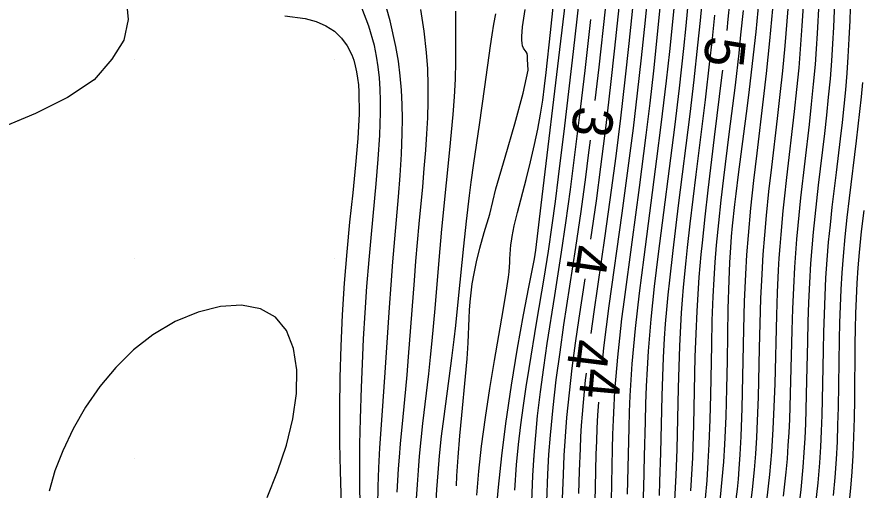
# Model space of a CAD drawing. Extents: x 2602990 to 2605851, y 618069 to 619180.
# Drawn here: x 2603504.11 to 2603546.38, y 618728.43 to 618752.12 of the extents above; entities that cross this region are included whole.
import ezdxf

# ---------------------------------------------------------------- set-up
doc = ezdxf.new("R2010")
doc.units = 0
for name, color, linetype in [('DTM Contours Major', 7, 'Continuous'), ('DTM Contours Major Text', 7, 'Continuous'), ('DTM Contours Minor', 7, 'Continuous'), ('DTM Contours Minor Text', 7, 'Continuous'), ('Exist DTM QL2 LIDAR Elevation Point', 7, 'Continuous')]:
    doc.layers.add(name, color=color, linetype=linetype)

msp = doc.modelspace()

# ---------------------------------------------------------------- linework, layer by layer
at = {"layer": 'DTM Contours Major'}
for points in [[(2603533.394, 618734.823), (2603533.474, 618735.547), (2603533.603, 618736.597), (2603533.742, 618737.653), (2603534.389, 618742.291), (2603534.722, 618744.789), (2603534.943, 618746.545), (2603535.151, 618748.306), (2603535.348, 618750.073), (2603535.543, 618751.946), (2603536.287, 618759.536)], [(2603524.101, 618727.991), (2603524.144, 618728.7), (2603524.194, 618729.409), (2603524.253, 618730.119), (2603524.333, 618730.94), (2603524.423, 618731.764), (2603524.714, 618734.251), (2603524.805, 618735.084), (2603524.886, 618735.893), (2603525.029, 618737.512), (2603525.23, 618739.939), (2603525.371, 618741.483), (2603525.6, 618743.805), (2603525.769, 618745.464), (2603525.855, 618746.346), (2603525.932, 618747.23), (2603525.997, 618748.114), (2603526.044, 618748.995), (2603526.069, 618749.872), (2603526.072, 618750.719), (2603526.06, 618752.402)], [(2603540.778, 618727.497), (2603540.897, 618728.462), (2603540.998, 618729.433), (2603541.065, 618730.242), (2603541.118, 618731.061), (2603541.159, 618731.898), (2603541.201, 618733.078), (2603541.259, 618735.529), (2603541.288, 618736.774), (2603541.326, 618738.014), (2603541.379, 618739.236), (2603541.438, 618740.22), (2603541.512, 618741.197), (2603541.6, 618742.178), (2603541.724, 618743.378), (2603541.861, 618744.593), (2603542.15, 618747.031), (2603542.288, 618748.233), (2603542.414, 618749.409), (2603542.533, 618750.669), (2603542.684, 618752.528)], [(2603533.008, 618726.521), (2603533.051, 618728.569), (2603533.089, 618730.23), (2603533.111, 618730.878), (2603533.138, 618731.525), (2603533.172, 618732.173), (2603533.213, 618732.825), (2603533.214, 618732.831)]]:
    msp.add_lwpolyline(points, dxfattribs=at)
at = {"layer": 'DTM Contours Minor'}
for points in [[(2603529.008, 618728.417), (2603529.101, 618729.684), (2603529.199, 618730.701), (2603529.315, 618731.693), (2603529.444, 618732.661), (2603529.582, 618733.604), (2603529.727, 618734.522), (2603530.123, 618736.887), (2603530.483, 618739.039), (2603530.694, 618740.389), (2603530.883, 618741.69), (2603531.044, 618742.873), (2603531.205, 618744.11), (2603531.52, 618746.67), (2603531.952, 618750.39), (2603532.604, 618756.134), (2603532.728, 618757.281), (2603532.846, 618758.417), (2603532.904, 618759.008)], [(2603503.501, 618758.444), (2603504.672, 618758.064), (2603505.794, 618757.541), (2603506.84, 618756.878), (2603507.779, 618756.075), (2603508.575, 618755.146), (2603509.19, 618754.123), (2603509.574, 618753.053), (2603509.68, 618751.979), (2603509.459, 618750.947), (2603508.863, 618750), (2603507.971, 618748.973), (2603506.648, 618748.083), (2603505.042, 618747.288), (2603503.3, 618746.547)], [(2603541.613, 618727.892), (2603541.764, 618729.206), (2603541.818, 618729.782), (2603541.865, 618730.35), (2603541.905, 618730.913), (2603541.939, 618731.474), (2603541.993, 618732.596), (2603542.032, 618733.738), (2603542.117, 618737.186), (2603542.154, 618738.318), (2603542.206, 618739.429), (2603542.242, 618740.031), (2603542.284, 618740.627), (2603542.331, 618741.219), (2603542.441, 618742.405), (2603542.503, 618743.005), (2603542.621, 618744.082), (2603543.003, 618747.382), (2603543.122, 618748.478), (2603543.228, 618749.56), (2603543.289, 618750.269), (2603543.393, 618751.667), (2603543.658, 618755.744)], [(2603528.879, 618741.121), (2603528.987, 618741.651), (2603529.151, 618742.331), (2603529.575, 618743.974), (2603529.796, 618744.855), (2603530, 618745.72), (2603530.164, 618746.501), (2603530.299, 618747.242), (2603530.412, 618747.954), (2603530.507, 618748.647), (2603530.59, 618749.335), (2603530.805, 618751.336), (2603531.221, 618755.282)], [(2603532.822, 618740.986), (2603533.095, 618742.911), (2603533.323, 618744.616), (2603533.581, 618746.676), (2603533.822, 618748.735), (2603534.024, 618750.556), (2603534.53, 618755.417)], [(2603529.996, 618740.004), (2603530.06, 618740.442), (2603530.341, 618742.696), (2603531.323, 618750.907), (2603531.734, 618754.38)], [(2603536.245, 618728.149), (2603536.275, 618728.863), (2603536.318, 618730.296), (2603536.385, 618733.149), (2603536.415, 618734.107), (2603536.455, 618735.064), (2603536.507, 618736.017), (2603536.558, 618736.744), (2603536.618, 618737.469), (2603536.686, 618738.197), (2603536.761, 618738.928), (2603536.928, 618740.417), (2603537.203, 618742.669), (2603537.779, 618747.24), (2603537.983, 618748.967), (2603538.175, 618750.709), (2603538.3, 618751.938), (2603538.542, 618754.46)], [(2603533.844, 618727.893), (2603533.9, 618730.493), (2603533.921, 618731.218), (2603533.948, 618731.941), (2603533.982, 618732.666), (2603534.024, 618733.394), (2603534.077, 618734.129), (2603534.161, 618735.075), (2603534.261, 618736.033), (2603534.374, 618736.999), (2603534.496, 618737.971), (2603534.882, 618740.841), (2603535.251, 618743.579), (2603535.587, 618746.191), (2603535.782, 618747.801), (2603535.966, 618749.417), (2603536.159, 618751.235), (2603536.459, 618754.271)], [(2603535.437, 618727.752), (2603535.465, 618728.541), (2603535.506, 618730.12), (2603535.546, 618731.867), (2603535.571, 618732.745), (2603535.603, 618733.624), (2603535.644, 618734.504), (2603535.698, 618735.385), (2603535.76, 618736.187), (2603535.832, 618736.991), (2603535.914, 618737.798), (2603536.005, 618738.611), (2603536.203, 618740.258), (2603537.013, 618746.592), (2603537.248, 618748.556), (2603537.466, 618750.536), (2603537.583, 618751.675), (2603537.809, 618754.013)], [(2603539.634, 618751.443), (2603539.693, 618752.01), (2603539.85, 618753.629)], [(2603544.078, 618727.771), (2603544.185, 618728.787), (2603544.271, 618729.793), (2603544.322, 618730.591), (2603544.359, 618731.384), (2603544.387, 618732.172), (2603544.421, 618733.745), (2603544.45, 618735.431), (2603544.47, 618736.334), (2603544.496, 618737.239), (2603544.531, 618738.145), (2603544.577, 618739.051), (2603544.637, 618739.957), (2603544.711, 618740.835), (2603544.797, 618741.711), (2603544.892, 618742.585), (2603545.099, 618744.325), (2603545.303, 618746.012), (2603545.397, 618746.831), (2603545.485, 618747.65), (2603545.565, 618748.47), (2603545.635, 618749.291), (2603545.694, 618750.116), (2603545.745, 618751.022), (2603545.784, 618751.932), (2603545.84, 618753.753)], [(2603522.159, 618727.631), (2603522.184, 618728.6), (2603522.219, 618729.538), (2603522.272, 618730.536), (2603522.383, 618732.167), (2603522.532, 618734.319), (2603522.744, 618737.572), (2603522.825, 618738.705), (2603522.914, 618739.847), (2603523.199, 618743.109), (2603523.281, 618744.181), (2603523.346, 618745.238), (2603523.385, 618746.28), (2603523.393, 618747.007), (2603523.382, 618747.728), (2603523.348, 618748.447), (2603523.288, 618749.167), (2603523.197, 618749.892), (2603523.072, 618750.626), (2603522.777, 618751.921), (2603522.413, 618753.235)], [(2603532.84, 618736.268), (2603532.989, 618737.343), (2603533.539, 618741.153), (2603533.856, 618743.436), (2603534.08, 618745.144), (2603534.315, 618747.051), (2603534.537, 618748.961), (2603534.735, 618750.783), (2603534.999, 618753.374)], [(2603543.197, 618727.341), (2603543.328, 618728.462), (2603543.433, 618729.568), (2603543.488, 618730.303), (2603543.531, 618731.029), (2603543.564, 618731.75), (2603543.59, 618732.468), (2603543.627, 618733.907), (2603543.668, 618735.86), (2603543.693, 618736.842), (2603543.726, 618737.824), (2603543.769, 618738.801), (2603543.827, 618739.771), (2603543.887, 618740.562), (2603543.957, 618741.347), (2603544.036, 618742.129), (2603544.21, 618743.689), (2603544.515, 618746.281), (2603544.617, 618747.191), (2603544.711, 618748.102), (2603544.797, 618749.013), (2603544.869, 618749.922), (2603544.924, 618750.765), (2603544.969, 618751.606), (2603545.041, 618753.285)], [(2603539.254, 618727.542), (2603539.392, 618728.953), (2603539.461, 618729.834), (2603539.516, 618730.713), (2603539.579, 618732.117), (2603539.62, 618733.515), (2603539.646, 618734.891), (2603539.688, 618737.507), (2603539.728, 618738.94), (2603539.769, 618739.817), (2603539.817, 618740.578), (2603539.859, 618741.116), (2603539.907, 618741.65), (2603540.018, 618742.72), (2603540.081, 618743.265), (2603540.201, 618744.23), (2603540.602, 618747.284), (2603540.737, 618748.335), (2603540.91, 618749.782), (2603541.079, 618751.365), (2603541.236, 618752.989)], [(2603542.46, 618728.115), (2603542.589, 618729.329), (2603542.646, 618729.996), (2603542.693, 618730.654), (2603542.732, 618731.305), (2603542.764, 618731.954), (2603542.811, 618733.252), (2603542.89, 618736.441), (2603542.921, 618737.503), (2603542.962, 618738.555), (2603543.017, 618739.592), (2603543.064, 618740.292), (2603543.12, 618740.986), (2603543.182, 618741.675), (2603543.324, 618743.054), (2603543.747, 618746.735), (2603543.858, 618747.739), (2603543.959, 618748.741), (2603544.047, 618749.735), (2603544.106, 618750.513), (2603544.156, 618751.286), (2603544.241, 618752.822)], [(2603521.309, 618726.64), (2603521.268, 618728.494), (2603521.256, 618729.566), (2603521.263, 618730.732), (2603521.291, 618731.99), (2603521.343, 618733.555), (2603521.392, 618734.75), (2603521.453, 618736), (2603521.528, 618737.293), (2603521.618, 618738.615), (2603521.725, 618739.952), (2603521.842, 618741.234), (2603522.084, 618743.765), (2603522.186, 618744.994), (2603522.26, 618746.187), (2603522.295, 618747.333), (2603522.294, 618747.923), (2603522.277, 618748.499), (2603522.24, 618749.061), (2603522.183, 618749.613), (2603522.101, 618750.154), (2603521.993, 618750.687), (2603521.72, 618751.652), (2603521.361, 618752.577)], [(2603523.138, 618728.331), (2603523.204, 618729.494), (2603523.245, 618730.073), (2603523.3, 618730.74), (2603523.427, 618732.09), (2603523.562, 618733.476), (2603523.628, 618734.189), (2603523.705, 618735.1), (2603523.991, 618738.913), (2603524.07, 618739.888), (2603524.237, 618741.751), (2603524.408, 618743.604), (2603524.488, 618744.525), (2603524.561, 618745.44), (2603524.617, 618746.257), (2603524.66, 618747.071), (2603524.685, 618747.884), (2603524.687, 618748.696), (2603524.662, 618749.511), (2603524.605, 618750.33), (2603524.48, 618751.407), (2603524.316, 618752.485)], [(2603525.06, 618727.614), (2603525.113, 618728.453), (2603525.176, 618729.299), (2603525.251, 618730.15), (2603525.356, 618731.134), (2603525.475, 618732.119), (2603525.862, 618735.033), (2603525.981, 618735.972), (2603526.061, 618736.666), (2603526.204, 618738.021), (2603526.462, 618740.633), (2603526.597, 618741.897), (2603526.75, 618743.183), (2603526.834, 618743.839), (2603526.963, 618744.791), (2603527.242, 618746.72), (2603527.52, 618748.615), (2603527.803, 618750.667), (2603527.883, 618751.216), (2603527.972, 618751.752), (2603528.074, 618752.277)], [(2603529.654, 618750), (2603529.652, 618750.168), (2603529.627, 618750.287), (2603529.588, 618750.372), (2603529.54, 618750.437), (2603529.489, 618750.493), (2603529.444, 618750.556), (2603529.401, 618750.66), (2603529.376, 618750.795), (2603529.365, 618750.959), (2603529.368, 618751.15), (2603529.383, 618751.369), (2603529.407, 618751.613), (2603529.53, 618752.49)], [(2603533.039, 618747.931), (2603533.233, 618749.606), (2603533.548, 618752.499)], [(2603534.654, 618728.215), (2603534.731, 618731.537), (2603534.757, 618732.338), (2603534.791, 618733.14), (2603534.833, 618733.945), (2603534.888, 618734.754), (2603534.96, 618735.629), (2603535.046, 618736.51), (2603535.144, 618737.397), (2603535.25, 618738.289), (2603535.479, 618740.09), (2603536.126, 618745.014), (2603536.34, 618746.718), (2603536.599, 618748.91), (2603536.761, 618750.39), (2603536.98, 618752.542)], [(2603538.555, 618728), (2603538.63, 618728.913), (2603538.69, 618729.819), (2603538.736, 618730.729), (2603538.78, 618731.957), (2603538.811, 618733.2), (2603538.861, 618735.689), (2603538.893, 618736.914), (2603538.938, 618738.112), (2603538.983, 618738.978), (2603539.039, 618739.833), (2603539.107, 618740.686), (2603539.212, 618741.808), (2603539.331, 618742.934), (2603539.461, 618744.055), (2603539.733, 618746.24), (2603540.044, 618748.7), (2603540.229, 618750.295), (2603540.327, 618751.215), (2603540.449, 618752.442)], [(2603540.088, 618727.976), (2603540.145, 618728.479), (2603540.195, 618728.98), (2603540.24, 618729.486), (2603540.293, 618730.215), (2603540.341, 618731.104), (2603540.388, 618732.531), (2603540.465, 618736.482), (2603540.504, 618737.86), (2603540.564, 618739.237), (2603540.622, 618740.202), (2603540.695, 618741.168), (2603540.821, 618742.543), (2603540.968, 618743.924), (2603541.129, 618745.3), (2603541.455, 618747.991), (2603541.605, 618749.285), (2603541.775, 618750.916), (2603541.925, 618752.524)], [(2603517.513, 618752.166), (2603518.532, 618752.039), (2603519.086, 618751.886), (2603519.571, 618751.671), (2603519.991, 618751.395), (2603520.345, 618751.059), (2603520.634, 618750.666), (2603520.861, 618750.215), (2603520.958, 618749.949), (2603521.039, 618749.665), (2603521.103, 618749.365), (2603521.153, 618749.048), (2603521.19, 618748.714), (2603521.214, 618748.362), (2603521.225, 618747.259), (2603521.165, 618746.032), (2603521.053, 618744.705), (2603520.91, 618743.301), (2603520.754, 618741.842), (2603520.607, 618740.351), (2603520.478, 618738.779), (2603520.378, 618737.204), (2603520.307, 618735.631), (2603520.262, 618734.067), (2603520.243, 618732.518), (2603520.252, 618730.78), (2603520.282, 618729.378), (2603520.353, 618727.126)], [(2603529.86, 618727.838), (2603529.918, 618729.161), (2603529.98, 618730.169), (2603530.06, 618731.159), (2603530.157, 618732.147), (2603530.299, 618733.348), (2603530.462, 618734.559), (2603530.639, 618735.772), (2603531.014, 618738.174), (2603531.35, 618740.336), (2603531.567, 618741.81), (2603531.798, 618743.478), (2603531.954, 618744.67), (2603532.251, 618747.072), (2603532.526, 618749.426), (2603532.811, 618751.992)], [(2603537.015, 618727.908), (2603537.052, 618728.545), (2603537.082, 618729.181), (2603537.128, 618730.459), (2603537.199, 618733.55), (2603537.228, 618734.591), (2603537.265, 618735.628), (2603537.316, 618736.656), (2603537.357, 618737.303), (2603537.404, 618737.947), (2603537.458, 618738.592), (2603537.584, 618739.898), (2603537.655, 618740.565), (2603537.79, 618741.755), (2603538.089, 618744.219), (2603538.552, 618747.97), (2603538.773, 618749.896), (2603538.879, 618750.87), (2603539.016, 618752.21)], [(2603526.095, 618728.641), (2603526.123, 618729.147), (2603526.185, 618730.082), (2603526.27, 618731.142), (2603526.364, 618732.174), (2603526.55, 618734.11), (2603526.626, 618734.992), (2603526.68, 618735.801), (2603526.73, 618737.029), (2603526.75, 618737.433), (2603526.78, 618737.852), (2603526.825, 618738.297), (2603526.886, 618738.757), (2603526.974, 618739.27), (2603527.097, 618739.854), (2603527.263, 618740.531), (2603527.482, 618741.319), (2603527.762, 618742.238), (2603528.074, 618743.513), (2603528.528, 618745.098), (2603529.018, 618746.766), (2603529.44, 618748.29), (2603529.687, 618749.444), (2603529.654, 618750)], [(2603537.821, 618728.383), (2603537.856, 618728.934), (2603537.912, 618730.037), (2603537.933, 618730.593), (2603537.966, 618731.701), (2603538.042, 618735.105), (2603538.078, 618736.245), (2603538.129, 618737.376), (2603538.162, 618737.944), (2603538.242, 618739.079), (2603538.341, 618740.227), (2603538.397, 618740.813), (2603538.534, 618742.109), (2603538.685, 618743.436), (2603539.009, 618746.1), (2603539.39, 618749.222), (2603539.416, 618749.455)], [(2603544.945, 618728.149), (2603545.031, 618729.063), (2603545.098, 618729.976), (2603545.145, 618730.838), (2603545.177, 618731.699), (2603545.199, 618732.559), (2603545.251, 618735.966), (2603545.271, 618736.797), (2603545.299, 618737.629), (2603545.336, 618738.464), (2603545.385, 618739.302), (2603545.447, 618740.143), (2603545.535, 618741.107), (2603545.638, 618742.074), (2603545.751, 618743.041), (2603546.108, 618745.912), (2603546.195, 618746.648), (2603546.276, 618747.378), (2603546.35, 618748.106), (2603546.416, 618748.835)], [(2603530.621, 618727.855), (2603530.67, 618729.224), (2603530.723, 618730.203), (2603530.795, 618731.184), (2603530.927, 618732.565), (2603531.09, 618733.953), (2603531.275, 618735.334), (2603531.473, 618736.698), (2603532.064, 618740.566), (2603532.329, 618742.382), (2603532.562, 618744.087), (2603532.706, 618745.197), (2603532.799, 618745.946)], [(2603545.734, 618727.712), (2603545.813, 618728.528), (2603545.879, 618729.345), (2603545.931, 618730.165), (2603545.971, 618731.09), (2603545.997, 618732.02), (2603546.012, 618732.952), (2603546.04, 618735.744), (2603546.055, 618736.504), (2603546.076, 618737.262), (2603546.106, 618738.021), (2603546.144, 618738.783), (2603546.194, 618739.55), (2603546.256, 618740.324), (2603546.359, 618741.373), (2603546.479, 618742.432)], [(2603527.109, 618728.168), (2603527.219, 618729.38), (2603527.355, 618730.62), (2603527.549, 618732.069), (2603527.77, 618733.51), (2603528.003, 618734.907), (2603528.435, 618737.411), (2603528.603, 618738.442), (2603528.693, 618739.082), (2603528.726, 618739.358), (2603528.75, 618739.604), (2603528.765, 618739.818), (2603528.77, 618740), (2603528.819, 618740.701), (2603528.843, 618740.895), (2603528.879, 618741.121)], [(2603528.069, 618727.081), (2603528.203, 618728.581), (2603528.365, 618730.146), (2603528.565, 618731.767), (2603528.844, 618733.673), (2603529.152, 618735.525), (2603529.454, 618737.202), (2603529.718, 618738.584), (2603529.996, 618740.004)], [(2603531.407, 618727.989), (2603531.444, 618729.207), (2603531.486, 618730.162), (2603531.544, 618731.111), (2603531.619, 618732.067), (2603531.742, 618733.294), (2603531.89, 618734.538), (2603532.056, 618735.786), (2603532.233, 618737.029), (2603532.528, 618739.008)], [(2603516.623, 618728.055), (2603517.146, 618729.353), (2603517.593, 618730.671), (2603517.914, 618731.986), (2603518.09, 618733.262), (2603518.105, 618734.454), (2603517.947, 618735.518), (2603517.601, 618736.408), (2603517.053, 618737.081), (2603516.288, 618737.505), (2603515.353, 618737.678), (2603514.297, 618737.616), (2603513.172, 618737.337), (2603512.027, 618736.859), (2603510.915, 618736.199), (2603509.951, 618735.443), (2603509.065, 618734.571), (2603508.261, 618733.606), (2603507.545, 618732.573), (2603506.924, 618731.496), (2603506.403, 618730.399), (2603506.015, 618729.384), (2603505.723, 618728.38)], [(2603532.224, 618728.262), (2603532.252, 618729.368), (2603532.294, 618730.516), (2603532.323, 618731.086), (2603532.357, 618731.657), (2603532.397, 618732.23), (2603532.444, 618732.808), (2603532.553, 618733.923), (2603532.594, 618734.283)]]:
    msp.add_lwpolyline(points, dxfattribs=at)
at = {"layer": 'Exist DTM QL2 LIDAR Elevation Point'}
for p, q in [((2603510, 618750), (2603510, 618750)), ((2603520, 618750), (2603520, 618750)), ((2603530, 618750), (2603530, 618750)), ((2603540, 618750), (2603540, 618750)), ((2603510, 618740), (2603510, 618740)), ((2603520, 618740), (2603520, 618740)), ((2603530, 618740), (2603530, 618740)), ((2603540, 618740), (2603540, 618740)), ((2603510, 618730), (2603510, 618730)), ((2603520, 618730), (2603520, 618730)), ((2603530, 618730), (2603530, 618730)), ((2603540, 618730), (2603540, 618730))]:
    msp.add_line(p, q, dxfattribs=at)

# ---------------------------------------------------------------- texts
at = {"layer": 'DTM Contours Major Text'}
msp.add_text('4', height=2, rotation=264.83, dxfattribs=at).set_placement((2603532.359, 618734.569))
at = {"layer": 'DTM Contours Minor Text'}
for s, rotation, p in [('5', 263.7654, (2603538.606, 618751.207)), ('3', 263.0891, (2603532.007, 618747.707)), ('4', 261.5543, (2603531.782, 618740.79)), ('4', 262.9339, (2603531.8, 618736.048))]:
    msp.add_text(s, height=2, rotation=rotation, dxfattribs=at).set_placement(p)

doc.saveas('drawing.dxf')
